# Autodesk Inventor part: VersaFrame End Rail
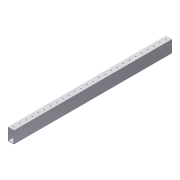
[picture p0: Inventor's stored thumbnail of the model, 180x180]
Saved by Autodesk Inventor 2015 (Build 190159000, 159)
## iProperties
Created: 2014-12
Part Number: VersaFrame End Rail
Material: Aluminum 6061
Document SubType Name: Modeling
Designer: Nemo
Density: 2.7 g/cm^3
Appearance: Aluminum - Flat
Length: 26.000 in
HoleOffset: 0.500 in
Author: Nemo
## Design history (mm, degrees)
sketch "Sketch1"
  geometry: L1 (12.7, -25.4)-(-12.7, -25.4); L2 (-12.7, -25.4)-(-12.7, 25.4); L3 (-12.7, 25.4)-(12.7, 25.4); L4 (12.7, 25.4)-(12.7, -25.4); L5 (12.7, -25.4)-(-12.7, 25.4); L6 (-12.7, -25.4)-(12.7, 25.4); L7 (10.16, 22.86)-(-10.16, 22.86); L8 (-10.16, 22.86)-(-10.16, -22.86); L9 (-10.16, -22.86)-(10.16, -22.86); L10 (10.16, -22.86)-(10.16, 22.86); 1 further point
  constraints: 20 end point, 4 parallel, 2 midpoint, 2 perpendicular, 1 horizontal, 3 other
  dimensions: "d0" = 25.4 distance of L2.end L3.end; "d1" = 50.8 distance of L1.end L2.end; "d2" = 2.54 distance between parallel lines of L3 L7
extrude "Extrusion1" new body sketch "Sketch1" taper "d4" = 0 deg; stored distance "Length" = 660.4
sketch "Sketch2"
  geometry: 3 further points
  constraints: 2 vertical alignment
  dimensions: "HoleOffset" = 12.7 distance of point (12.7, 330.2) point (12.7, 342.9); "d6" = 12.7 distance of point (12.7, 330.2) point (12.7, 317.5) (computed from HoleOffset)
hole "Hole1" sketch "Sketch2" at (12.7, 342.9), (12.7, 317.5) diameter "d7" = 4.1656; stored, may be unused: countersink angle "d11" = 82 deg, drill point angle "d13" = 118 deg; dims "d8" = 19.05, "d9" = 9.525, "d10" = 6.35, "d12" = 25.4
body "Solid1"
pattern_linear "Rectangular Pattern1" dims "d16" = 50.8
